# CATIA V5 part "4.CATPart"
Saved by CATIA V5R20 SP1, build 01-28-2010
Part number: 4
Publications: "G", "H", "Droite.1", "Droite.2", "Droite.3", "HG", "Plan.1", "G1", "H1", "Droite.4", "Droite.5", "Droite.6", "Droite.7", "Plan.2"
Bounding box of the stored display mesh (mm): x 0 to 0, y 46.109 to 67.644, z -84.832 to 19.338
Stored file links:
  C:\Users\Geoffray\Documents\Ifma\IAO\Exercice IAO\Catia\4.CATPart
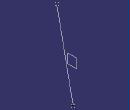
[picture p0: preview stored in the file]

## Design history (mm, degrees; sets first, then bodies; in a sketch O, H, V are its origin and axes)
Parameters
  HK = 50 mm
  HG = 120 mm
Body1 (main body)
  Point1 to Point3 "K": stored without definition
  Point4 "B": stored without definition
  Point5 "B": stored without definition
  Point6 "D": stored without definition
  Point7 "D": stored without definition
  Point8 "G": stored without definition
  Point9 "H": stored without definition
  Sketch1 on yz-plane, origin (0, 0, 0), H (0, 1, 0), V (0, 0, 1)
    circle A1 centre (20, -100) radius 50
    point P1 (20, -100)
    reference projected point E1 (20, -100) from Point1
    reference projected point E2 (20, -100) from Point3
    point P2 (-12.5723, -62.0652)
    point P3 (67.6439, -84.8322)
    circle A2 centre (43.3503, 32.683) radius 120
    point P4 (43.3503, 32.683)
    reference projected point E3 (67.6439, -84.8322) from Point9
    distance E2 A1 = 50 {= HK}
    distance P4 A2 = 120 {= HG}
    coincidence: P1 E1, A1 P2, A1 P3, E3 A2
  Point10 "D": stored without definition
  Plane1: type Offset, RefPlane yz-plane, Offset 0
  Point11 "G": stored without definition
  Point12 "G": (0, 0, 0), relative to Point11
  Point13 "H": (0, 0, 0), relative to Sketch1.P3
  Point14 "B": stored without definition
  Line1: type PtDir, RefPoint Point14, Direction yz-plane, Start -20, End 20
  Line2: type PtDir, RefPoint Point13, Direction yz-plane, Start -20, End 20
  Line3: type PtPt, FirstPoint Point12, SecondPoint Sketch1.P3
  Line4: type PtDir, RefPoint Point12, Direction yz-plane, Start -20, End 20
  Plane2: type Offset, RefPlane Plane1, Offset 2, reversed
